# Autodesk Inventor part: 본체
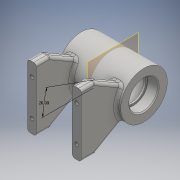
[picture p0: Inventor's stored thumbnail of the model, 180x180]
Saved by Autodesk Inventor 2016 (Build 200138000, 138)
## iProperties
Created: 2018-05
Part Number: 본체
Material: 일반
Document SubType Name: Modeling
Designer: 201-08
Density: 1 g/cm^3
Appearance: 기본값
Author: 201-08
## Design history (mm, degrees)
sketch "스케치1"
  geometry: C1 r 26 at (0, 0); 1 further point
  constraints: 1 centre point, 1 coincident
  dimensions: "d0" = 52 diameter of C1
extrude "돌출1" new body sketch "스케치1" stored distance "d2" = 70; taper "d3" = 0 deg
node "작업 평면2"
  node "작업 평면1"
sketch "스케치2"
  geometry: L1 (0, 0)-(-65, 0); L2 (-65, 0)-(-65, -35); L3 (-65, -35)-(-50, -35); L4 (-50, -35)-(10.622, 0); L5 (-65, 0)-(-65, 35); L6 (-65, 35)-(-50, 35); L7 (-50, 35)-(10.622, 0)
  constraints: 14 end point, 2 symmetric about line, 1 horizontal, 1 perpendicular, 1 point on line, 1 vertical
  dimensions: "d6" = 65 distance of L1.start L1.end; "d7" = 35 distance of L1.end L2.end; "d8" = 15 distance of L2.end L3.end; "d9" = 150 deg angle of L4 L3; "d10" = 30 deg angle of L6 L7 (derived)
extrude "돌출2" join sketch "스케치2" distance "d11" = 10; taper "d12" = 0 deg
sketch "스케치3"
  geometry: L1 (0, 70)-(0, 0) reference; L2 (0, 70)-(-10, 70) reference; L3 (-10, 0)-(-10, 70) reference; L4 (0, 0)-(-10, 0) reference; L5 (40, 70)-(40, 0) reference; L6 (40, 0)-(50, 0) reference; L7 (50, 0)-(50, 70) reference; L8 (40, 70)-(50, 70) reference; 5 further points
  constraints: 2 horizontal alignment, 2 vertical alignment
  dimensions: "d13" = 60 distance between parallel lines of L7 L3 (derived); "d14" = 40 distance of point (-5, 55) point (-5, 15); "d15" = 5 horizontal distance of L3.start point (-5, 15); "d16" = 20 vertical distance of point (20, 35) point (45, 55)
hole "구멍1" sketch "스케치3" at (-5, 55), (-5, 15), (45, 55), (45, 15) diameter "d17" = 4.134; stored, may be unused: countersink angle "d21" = 90 deg, drill point angle "d23" = 118 deg; dims "d18" = 8, "d19" = 4, "d20" = 2, "d22" = 10
fillet "모깎기1" dims "d24" = 3
sketch "스케치4"
  geometry: C1 r 14 at (0, 0); 1 further point
  constraints: 1 centre point, 1 coincident
  dimensions: "d25" = 28 diameter of C1
extrude "돌출3" cut sketch "스케치4" stored distance "d26" = 10; taper "d27" = 0 deg
sketch "스케치5"
  geometry: C1 r 16 at (0, 0); 1 further point
  constraints: 1 centre point, 1 coincident
  dimensions: "d28" = 32 diameter of C1
extrude "돌출4" cut sketch "스케치5" distance "d29" = 12; taper "d30" = 0 deg
sketch "스케치6"
  geometry: C1 r 21 at (0, 0); 1 further point
  constraints: 1 centre point, 1 coincident
  dimensions: "d31" = 42 diameter of C1
extrude "돌출5" cut sketch "스케치6" stored distance "d32" = 42; taper "d33" = 0 deg
fillet "모깎기2" dims "d34" = 0.3
fillet "모깎기3" dims "d35" = 3
node "작업 평면3"
sketch "스케치7"
  geometry: C1 r 5 at (0, 0); 1 further point
  constraints: 1 centre point, 1 coincident
  dimensions: "d36" = 10 diameter of C1
extrude "돌출6" join sketch "스케치7" stored distance "d37" = 6; taper "d38" = 0 deg
fillet "모깎기4" dims "d39" = 2
sketch "스케치8"
  geometry: 2 further points
  constraints: 1 coincident
hole "구멍2" sketch "스케치8" at (0, 0) diameter "d40" = 5.188; stored, may be unused: countersink angle "d44" = 90 deg, drill point angle "d46" = 118 deg; dims "d41" = 10, "d42" = 4, "d43" = 2, "d45" = 10
chamfer "모따기1" distance "d47" = 1; stored, may be unused: second distance "d48" = 2, angle "d49" = 45 deg
sketch "스케치9"
  geometry: L1 (0, 0)-(-21, 0); L2 (0, 0)-(-19.734, 7.182); L3 (0, 0)-(21.165, 0); A1 r 21 centre (0, 0) between (-19.734, 7.182) and (-21, 0) reference; 1 further point
  constraints: 6 end point, 2 horizontal, 2 point on circle, 1 coincident
  dimensions: "d51" = 20 deg angle of L1 L2
node "솔리드1"
mirror "대칭1"
mirror "대칭2"
node "투영된 루프1"
node "투영된 루프2"
other parameters: "d4" = 0
